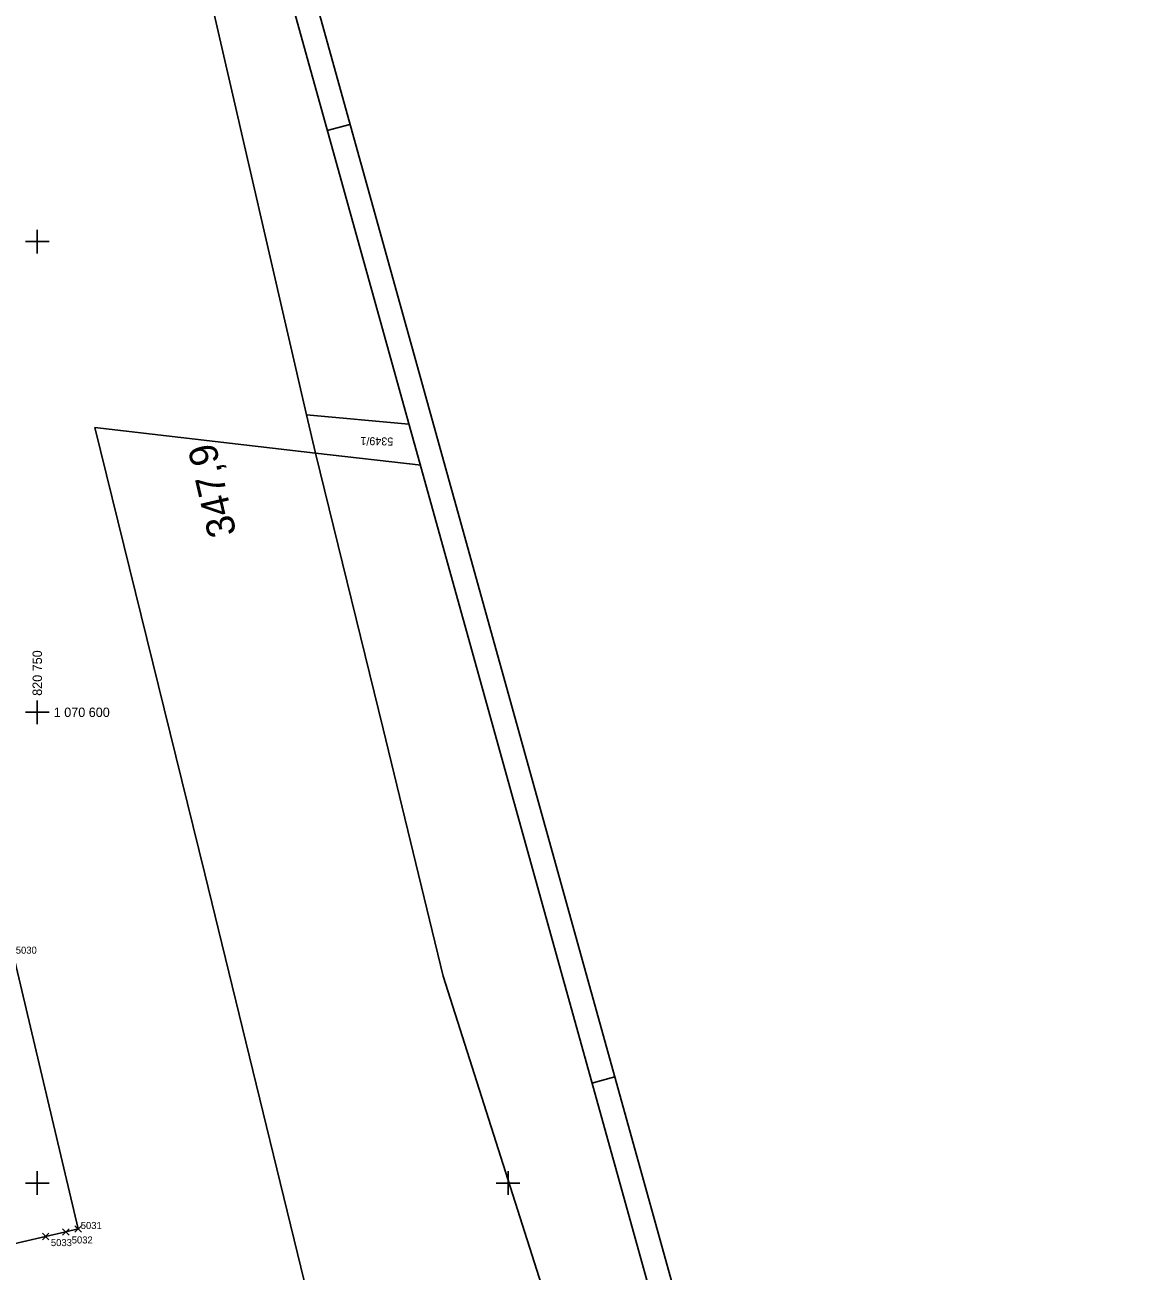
# Model space of a CAD drawing. Extents: x -821172 to -820632, y -1070921 to -1069931.
# Drawn here: x -820751.3 to -820632.5, y -1070659.4 to -1070527 of the extents above; entities that cross this region are included whole.
import ezdxf

# ---------------------------------------------------------------- set-up
doc = ezdxf.new("R2010")
doc.units = 0
for name, color, linetype in [('Ram', 7, 'Continuous'), ('Sit', 7, 'Continuous'), ('Sttaniceni a namezniky', 7, 'Continuous'), ('VB_bod_DZ', 7, 'Continuous'), ('Vrstva 52', 7, 'Continuous'), ('Vrstva 53', 7, 'Continuous'), ('Vrstva 55', 7, 'Continuous'), ('Vrstva 57', 7, 'Continuous')]:
    doc.layers.add(name, color=color, linetype=linetype)

msp = doc.modelspace()

# ---------------------------------------------------------------- linework, layer by layer
at = {"layer": 'Ram'}
for p, q in [((-820716.79, -1070537.55), (-820719.2, -1070538.22)), ((-820688.68, -1070638.72), (-820691.09, -1070639.39))]:
    msp.add_line(p, q, dxfattribs=at)
for points in [[(-820857.35, -1070031.72), (-820632.46, -1070841.06)], [(-820859.09, -1070034.8), (-820635.54, -1070839.32), (-820916.88, -1070917.49)]]:
    msp.add_lwpolyline(points, dxfattribs=at)
at = {"layer": 'Sit'}
for p, q in [((-820750, -1070548.75), (-820750, -1070550)), ((-820751.25, -1070550), (-820750, -1070550)), ((-820748.75, -1070550), (-820750, -1070550)), ((-820750, -1070551.25), (-820750, -1070550)), ((-820750, -1070598.75), (-820750, -1070600)), ((-820751.25, -1070600), (-820750, -1070600)), ((-820748.75, -1070600), (-820750, -1070600)), ((-820750, -1070601.25), (-820750, -1070600)), ((-820750, -1070648.75), (-820750, -1070650)), ((-820700, -1070648.75), (-820700, -1070650)), ((-820751.25, -1070650), (-820750, -1070650)), ((-820748.75, -1070650), (-820750, -1070650)), ((-820750, -1070651.25), (-820750, -1070650)), ((-820701.25, -1070650), (-820700, -1070650)), ((-820698.75, -1070650), (-820700, -1070650)), ((-820700, -1070651.25), (-820700, -1070650))]:
    msp.add_line(p, q, dxfattribs=at)
at = {"layer": 'VB_bod_DZ'}
for p, q in [((-820749.45, -1070656.03), (-820748.77, -1070655.34)), ((-820748.77, -1070656.03), (-820749.45, -1070655.34)), ((-820747.31, -1070655.54), (-820746.62, -1070654.85)), ((-820746.62, -1070655.54), (-820747.31, -1070654.85)), ((-820746, -1070655.22), (-820745.31, -1070654.53)), ((-820745.31, -1070655.22), (-820746, -1070654.53))]:
    msp.add_line(p, q, dxfattribs=at)
at = {"layer": 'Vrstva 52'}
msp.add_lwpolyline([(-820758.47, -1070564.86), (-820757.45, -1070567.88), (-820755.31, -1070577.01), (-820756.05, -1070579.63), (-820755.02, -1070594.22), (-820756.59, -1070604.3), (-820752.56, -1070625.64), (-820745.66, -1070654.88), (-820746.96, -1070655.19), (-820749.11, -1070655.68), (-820754.03, -1070656.83), (-820753.84, -1070657.98), (-820750.47, -1070669.89)], dxfattribs=at)
at = {"layer": 'Vrstva 53'}
for p, q in [((-820751, -1070439.83), (-820721.42, -1070568.42)), ((-820721.42, -1070568.42), (-820720.44, -1070572.46))]:
    msp.add_line(p, q, dxfattribs=at)
msp.add_lwpolyline([(-820720.44, -1070572.46), (-820743.88, -1070569.76), (-820732.22, -1070617.16), (-820718.37, -1070673.87), (-820707.85, -1070716.96), (-820694.56, -1070770.81), (-820679.24, -1070835.68), (-820677.73, -1070841.82), (-820675.61, -1070850.43)], dxfattribs=at)
at = {"layer": 'Vrstva 55'}
for p, q in [((-820721.42, -1070568.42), (-820751, -1070439.83)), ((-820720.44, -1070572.46), (-820721.42, -1070568.42)), ((-820710.54, -1070569.39), (-820721.42, -1070568.42)), ((-820709.22, -1070573.76), (-820720.44, -1070572.46))]:
    msp.add_line(p, q, dxfattribs=at)
for points in [[(-820720.44, -1070572.46), (-820743.88, -1070569.76), (-820732.22, -1070617.16), (-820718.37, -1070673.87), (-820707.85, -1070716.96), (-820694.56, -1070770.81), (-820679.24, -1070835.68), (-820675.61, -1070850.43)], [(-820643.09, -1070841.4), (-820651.05, -1070805.08), (-820667.4, -1070753.6), (-820685.24, -1070696.04), (-820706.9, -1070628.02), (-820713.28, -1070601.74), (-820720.44, -1070572.46)]]:
    msp.add_lwpolyline(points, dxfattribs=at)

# ---------------------------------------------------------------- texts
at = {"layer": 'Sit'}
msp.add_text('820 750', height=1, rotation=90, dxfattribs=at).set_placement((-820749.5, -1070598.25))
msp.add_text('1 070 600', height=1, dxfattribs=at).set_placement((-820748.25, -1070600.5))
at = {"layer": 'Sttaniceni a namezniky'}
msp.add_text('347,9', height=3, rotation=103.1701, dxfattribs=at).set_placement((-820728.83, -1070581.02))
at = {"layer": 'VB_bod_DZ'}
for s, p in [(' 5030', (-820752.56, -1070625.64)), (' 5031', (-820745.66, -1070654.88)), (' 5032', (-820746.62, -1070656.42)), (' 5033', (-820748.83, -1070656.7))]:
    msp.add_text(s, height=0.75, dxfattribs=at).set_placement(p)
at = {"layer": 'Vrstva 57'}
msp.add_text('5349/1', height=0.85, rotation=178.9097, dxfattribs=at).set_placement((-820712.19, -1070570.82))

doc.saveas('drawing.dxf')
